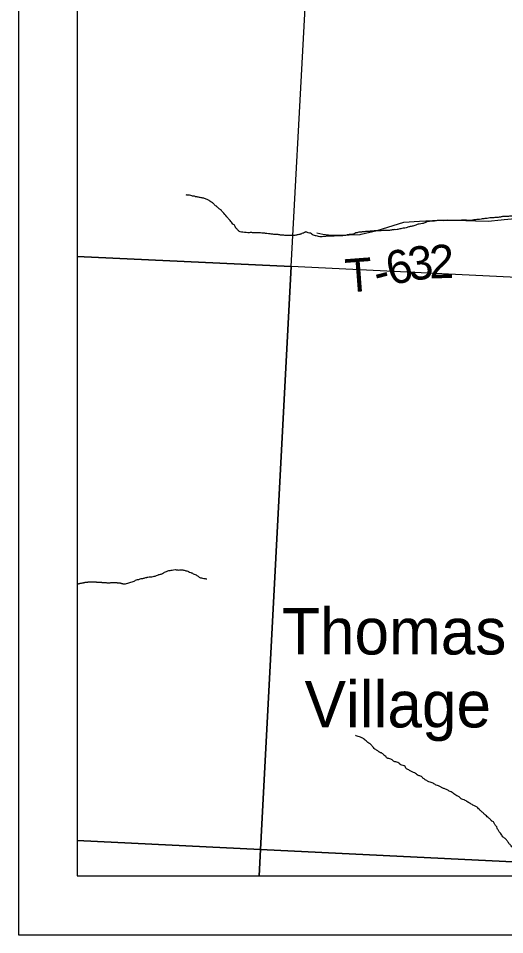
# Model space of a CAD drawing. Extents: x -20.2 to 34, y 0 to 22.
# Drawn here: x 2 to 2.827, y 14 to 15.559 of the extents above; entities that cross this region are included whole.
import ezdxf

# ---------------------------------------------------------------- set-up
doc = ezdxf.new("R2010")
doc.units = 0
for name, color, linetype in [('Default', 7, 'Continuous'), ('GM_X_Minor_River', 7, 'Continuous'), ('GM_X_Township_Road', 7, 'Continuous'), ('GM_X_Township_Road_Text', 7, 'Continuous'), ('GM_X_Unincorporated_Text', 7, 'Continuous'), ('SH_Cut_Line', 7, 'Continuous'), ('SH_Data', 7, 'Continuous')]:
    doc.layers.add(name, color=color, linetype=linetype)

msp = doc.modelspace()

# ---------------------------------------------------------------- linework, layer by layer
at = {"layer": 'Default'}
msp.add_lwpolyline([(4.5, 19.1063), (4.129, 19.1285), (4.084, 19.1299), (2.9253, 19.1951), (2.1, 19.2514), (2.1, 14.1), (5.3953, 14.1)], dxfattribs=at)
for points in [[(2.1, 16.1594), (2.1, 15.1538), (2.4641, 15.1369), (2.5061, 15.9134), (2.5172, 16.1333)], [(2.1, 15.1538), (2.1, 14.1602), (2.4117, 14.1451), (2.4641, 15.1369)], [(3.3273, 14.1), (3.4615, 14.1), (3.4877, 14.5012), (3.5149, 14.9006), (3.5228, 15.0852), (2.4641, 15.1369), (2.4117, 14.1451)], [(2.1, 14.1602), (2.1, 14.1), (2.4093, 14.1), (2.4117, 14.1451)], [(2.4093, 14.1), (3.3273, 14.1), (2.4117, 14.1451)]]:
    msp.add_lwpolyline(points, close=True, dxfattribs=at)
at = {"layer": 'GM_X_Minor_River'}
for points in [[(2.5301, 15.1883), (2.5251, 15.1883), (2.5191, 15.1876), (2.5103, 15.1876), (2.5065, 15.1888), (2.5035, 15.1895), (2.4997, 15.1914), (2.497, 15.1933), (2.4951, 15.1937), (2.4906, 15.1952), (2.4887, 15.1956), (2.4849, 15.1937), (2.4822, 15.193), (2.4803, 15.1918), (2.4784, 15.1915), (2.4754, 15.1907), (2.4731, 15.1903), (2.4704, 15.1896), (2.467, 15.1896), (2.4647, 15.1896), (2.4549, 15.1896), (2.4515, 15.19), (2.4458, 15.1904), (2.4401, 15.1912), (2.4363, 15.1915), (2.4344, 15.1915), (2.4283, 15.1923), (2.4226, 15.1927), (2.4203, 15.1931), (2.4177, 15.1935), (2.4158, 15.1935), (2.4082, 15.1942), (2.4044, 15.1939), (2.4021, 15.1943), (2.4002, 15.1939), (2.3983, 15.1943), (2.3926, 15.1943), (2.382, 15.1951), (2.3774, 15.1958), (2.3732, 15.1989), (2.3713, 15.2011), (2.3691, 15.2034), (2.3683, 15.2061), (2.3649, 15.2091), (2.3622, 15.2122), (2.3577, 15.2175), (2.3562, 15.2194), (2.3494, 15.2274), (2.3471, 15.2297), (2.3452, 15.2323), (2.3425, 15.2342), (2.3387, 15.2377), (2.3368, 15.2392), (2.3342, 15.2411), (2.3323, 15.2434), (2.3285, 15.2464), (2.3258, 15.2479), (2.3236, 15.2498), (2.3209, 15.251), (2.3183, 15.2517), (2.3152, 15.2529), (2.3126, 15.2536), (2.3091, 15.254), (2.3065, 15.2548), (2.3042, 15.2552), (2.3015, 15.2556), (2.2993, 15.2563), (2.2974, 15.2563), (2.2951, 15.2571), (2.2913, 15.2579), (2.2879, 15.2582), (2.2856, 15.2586)], [(2.8825, 15.2091), (2.8883, 15.2093), (2.8868, 15.2131), (2.883, 15.2154), (2.8807, 15.2166), (2.8784, 15.2173), (2.8765, 15.2181), (2.8742, 15.2185), (2.8723, 15.2193), (2.8685, 15.2193), (2.8647, 15.22), (2.8613, 15.2212), (2.8568, 15.2219), (2.8526, 15.2227), (2.8499, 15.2231), (2.8461, 15.2231), (2.8439, 15.2235), (2.842, 15.2235), (2.8397, 15.2227), (2.8366, 15.2223), (2.8306, 15.222), (2.8245, 15.222), (2.8222, 15.2216), (2.8199, 15.2209), (2.8176, 15.2205), (2.8116, 15.2201), (2.8051, 15.2194), (2.8017, 15.2194), (2.7971, 15.2186), (2.793, 15.2182), (2.7869, 15.2175), (2.7819, 15.2167), (2.7797, 15.2168), (2.7766, 15.216), (2.7743, 15.216), (2.7724, 15.2156), (2.7664, 15.2153), (2.7493, 15.2153), (2.7462, 15.2149), (2.7432, 15.2153), (2.7402, 15.2149), (2.7371, 15.2153), (2.7345, 15.2149), (2.7318, 15.2153), (2.7276, 15.2153), (2.7253, 15.2149), (2.7136, 15.215), (2.7102, 15.2146), (2.7071, 15.2142), (2.7037, 15.2138), (2.7007, 15.2139), (2.6984, 15.2135), (2.6957, 15.2131), (2.6923, 15.2116), (2.687, 15.2097), (2.6817, 15.209), (2.6782, 15.2082), (2.6756, 15.2071), (2.6725, 15.2059), (2.6665, 15.2048), (2.6611, 15.2033), (2.6573, 15.2022), (2.6543, 15.2022), (2.6501, 15.201), (2.6471, 15.2003), (2.644, 15.1995), (2.6395, 15.1995), (2.6372, 15.1992), (2.6345, 15.1988), (2.6277, 15.198), (2.6224, 15.198), (2.6167, 15.1977), (2.6083, 15.1977), (2.6049, 15.1973), (2.6023, 15.1969), (2.5996, 15.1969), (2.5966, 15.1966), (2.5939, 15.1966), (2.5905, 15.1962), (2.5882, 15.1958), (2.5859, 15.1958), (2.5836, 15.1955), (2.581, 15.1955), (2.5787, 15.1951), (2.576, 15.1943), (2.5719, 15.1932), (2.57, 15.1921), (2.5639, 15.1913), (2.5612, 15.1909), (2.5593, 15.1906), (2.5563, 15.1898), (2.5525, 15.1894), (2.5498, 15.1891), (2.5399, 15.1891), (2.5365, 15.1887), (2.5335, 15.1887), (2.5301, 15.1883)], [(2.1822, 14.597), (2.186, 14.5981), (2.1933, 14.6004), (2.1967, 14.6015), (2.1993, 14.603), (2.2028, 14.6042), (2.205, 14.6045), (2.2073, 14.6057), (2.2107, 14.606), (2.213, 14.6064), (2.2153, 14.6072), (2.2183, 14.6079), (2.2202, 14.6083), (2.2244, 14.6087), (2.229, 14.6094), (2.2324, 14.6102), (2.2351, 14.6109), (2.2381, 14.6124), (2.24, 14.6128), (2.243, 14.6136), (2.2468, 14.6155), (2.2487, 14.617), (2.2522, 14.6177), (2.2541, 14.6189), (2.2579, 14.6196), (2.2613, 14.6204), (2.2666, 14.6211), (2.2727, 14.6204), (2.2761, 14.6207), (2.2799, 14.6207), (2.2822, 14.62), (2.2848, 14.6192), (2.2867, 14.6188), (2.2894, 14.618), (2.2932, 14.6161), (2.2951, 14.6154), (2.2974, 14.6142), (2.3008, 14.6127), (2.3034, 14.6112), (2.3057, 14.6097), (2.3099, 14.6074), (2.3129, 14.6066), (2.3175, 14.6058), (2.3205, 14.6055)], [(2.6215, 14.3053), (2.62, 14.3076), (2.6143, 14.3103), (2.6113, 14.3125), (2.6064, 14.3156), (2.6037, 14.3183), (2.5999, 14.3232), (2.598, 14.3247), (2.5958, 14.3259), (2.5931, 14.3281), (2.5912, 14.33), (2.5855, 14.3342), (2.5802, 14.3365), (2.576, 14.338), (2.5734, 14.3392)], [(2.9149, 14.1188), (2.9106, 14.1199), (2.9068, 14.1203), (2.9011, 14.1214), (2.8989, 14.1225), (2.897, 14.1252), (2.8943, 14.1271), (2.8924, 14.129), (2.8901, 14.1309), (2.8879, 14.1347), (2.8856, 14.1362), (2.8829, 14.1381), (2.8803, 14.1393), (2.8784, 14.14), (2.8746, 14.1412), (2.8723, 14.1416), (2.8674, 14.1416), (2.8643, 14.1412), (2.8621, 14.1412), (2.8598, 14.1408), (2.8564, 14.1408), (2.8545, 14.1412), (2.8518, 14.1416), (2.8499, 14.1428), (2.8442, 14.1458), (2.8419, 14.1481), (2.8393, 14.1496), (2.837, 14.1523), (2.8351, 14.1542), (2.8317, 14.1591), (2.8275, 14.1637), (2.8237, 14.1667), (2.8222, 14.1694), (2.8196, 14.1728), (2.8177, 14.1751), (2.8165, 14.177), (2.815, 14.1793), (2.8135, 14.1835), (2.8116, 14.1857), (2.809, 14.1899), (2.8078, 14.1918), (2.8052, 14.1933), (2.8021, 14.1968), (2.8002, 14.1983), (2.7946, 14.2032), (2.7908, 14.2067), (2.7885, 14.2086), (2.7858, 14.2112), (2.7839, 14.2127), (2.7813, 14.2158), (2.7767, 14.2188), (2.7745, 14.2196), (2.7714, 14.2215), (2.7688, 14.223), (2.7657, 14.2246), (2.76, 14.2284), (2.7578, 14.2295), (2.7543, 14.2303), (2.7517, 14.2322), (2.7494, 14.2345), (2.7456, 14.2364), (2.7422, 14.2386), (2.7392, 14.2409), (2.7358, 14.2428), (2.7327, 14.2444), (2.7301, 14.2459), (2.7278, 14.247), (2.7251, 14.2482), (2.7229, 14.2489), (2.7206, 14.2501), (2.7187, 14.2508), (2.7145, 14.2531), (2.7107, 14.2543), (2.7054, 14.2577), (2.6982, 14.26), (2.6959, 14.2611), (2.6929, 14.263), (2.691, 14.2642), (2.6887, 14.2657), (2.6853, 14.2691), (2.68, 14.271), (2.6739, 14.2752), (2.6705, 14.2764), (2.6686, 14.2775), (2.6663, 14.2786), (2.6637, 14.2802), (2.6591, 14.2832), (2.6576, 14.2863), (2.6504, 14.2889), (2.6485, 14.2905), (2.642, 14.2939), (2.639, 14.2946), (2.6367, 14.2965), (2.6318, 14.2992), (2.6284, 14.3), (2.6246, 14.303), (2.6215, 14.3053)]]:
    msp.add_spline(points, degree=3, dxfattribs=at)
msp.add_open_spline([(2.1, 14.5966), (2.1003, 14.5966), (2.1006, 14.5967), (2.101, 14.5967), (2.1017, 14.5969), (2.1025, 14.5973), (2.1032, 14.5975), (2.104, 14.5976), (2.1048, 14.5977), (2.1055, 14.5979), (2.1069, 14.5981), (2.1083, 14.5984), (2.1097, 14.5986), (2.1107, 14.5988), (2.1117, 14.5992), (2.1127, 14.5994), (2.1139, 14.5995), (2.115, 14.5996), (2.1162, 14.5997), (2.1172, 14.5999), (2.1182, 14.6), (2.1192, 14.6001), (2.1201, 14.6002), (2.121, 14.6001), (2.1219, 14.6001), (2.1231, 14.6002), (2.1244, 14.6004), (2.1257, 14.6005), (2.1265, 14.6005), (2.1274, 14.6005), (2.1283, 14.6005), (2.1296, 14.6004), (2.1309, 14.6002), (2.1321, 14.6001), (2.133, 14.6), (2.1339, 14.5998), (2.1348, 14.5997), (2.1364, 14.5995), (2.1381, 14.5998), (2.1397, 14.5997), (2.141, 14.5996), (2.1422, 14.5994), (2.1435, 14.5993), (2.1441, 14.5993), (2.1448, 14.5993), (2.1454, 14.5993), (2.1467, 14.5992), (2.1479, 14.599), (2.1492, 14.5989), (2.152, 14.5988), (2.1548, 14.5988), (2.1576, 14.5989), (2.1585, 14.599), (2.1593, 14.5993), (2.1602, 14.5993), (2.1612, 14.5993), (2.1622, 14.5993), (2.1633, 14.5993), (2.1639, 14.5993), (2.1645, 14.5993), (2.1652, 14.5993), (2.1659, 14.5993), (2.1667, 14.599), (2.1674, 14.5989), (2.1687, 14.5988), (2.17, 14.5986), (2.1712, 14.5985), (2.1724, 14.5984), (2.1735, 14.5983), (2.1747, 14.5981), (2.1753, 14.598), (2.1759, 14.5975), (2.1765, 14.5974), (2.1777, 14.5971), (2.1788, 14.597), (2.18, 14.597), (2.1807, 14.597), (2.1815, 14.597), (2.1822, 14.597)], degree=3, dxfattribs=at)
at = {"layer": 'GM_X_Township_Road'}
for points in [[(2.5831, 15.1919), (2.6101, 15.1983), (2.6552, 15.212), (2.6822, 15.214), (2.715, 15.2159), (2.7445, 15.2157), (2.7775, 15.2144), (2.7986, 15.2142), (2.8212, 15.2161), (2.8259, 15.2166)], [(2.8259, 15.2166), (2.8383, 15.218), (2.8492, 15.2186), (2.8588, 15.218), (2.8732, 15.2173)], [(2.5077, 15.1941), (2.5175, 15.1917), (2.5276, 15.1907), (2.5445, 15.1902), (2.5812, 15.1915), (2.5831, 15.1919)]]:
    msp.add_lwpolyline(points, dxfattribs=at)
at = {"layer": 'SH_Cut_Line'}
msp.add_lwpolyline([(5.7735, 14.1), (8.9, 14.1), (8.9, 20.9), (2.1, 20.9), (2.1, 14.1), (5.3953, 14.1), (5.7268, 14.1076)], close=True, dxfattribs=at)
at = {"layer": 'SH_Data'}
for p, q in [((2, 21), (2, 14)), ((2.1, 20.9), (2.1, 14.1)), ((2.1, 14.1), (8.9, 14.1)), ((2.1, 14.1), (2.1, 14.1)), ((2, 14), (9, 14))]:
    msp.add_line(p, q, dxfattribs=at)

# ---------------------------------------------------------------- texts
at = {"layer": 'GM_X_Township_Road_Text'}
for s, rotation, p in [('3', 6.7861, (2.6658, 15.1123)), ('2', 1.5406, (2.6992, 15.1164)), ('6', 15.222, (2.6342, 15.1036)), ('T', 4.3241, (2.5577, 15.0924)), ('-', 14.8525, (2.6113, 15.0975))]:
    msp.add_text(s, height=0.0568, rotation=rotation, dxfattribs=at).set_placement(p)
at = {"layer": 'GM_X_Unincorporated_Text'}
for s, p in [('Thomas', (2.4483, 14.4767)), ('Village', (2.4867, 14.3526))]:
    msp.add_text(s, height=0.07898, rotation=0, dxfattribs=at).set_placement(p)

doc.saveas('drawing.dxf')
